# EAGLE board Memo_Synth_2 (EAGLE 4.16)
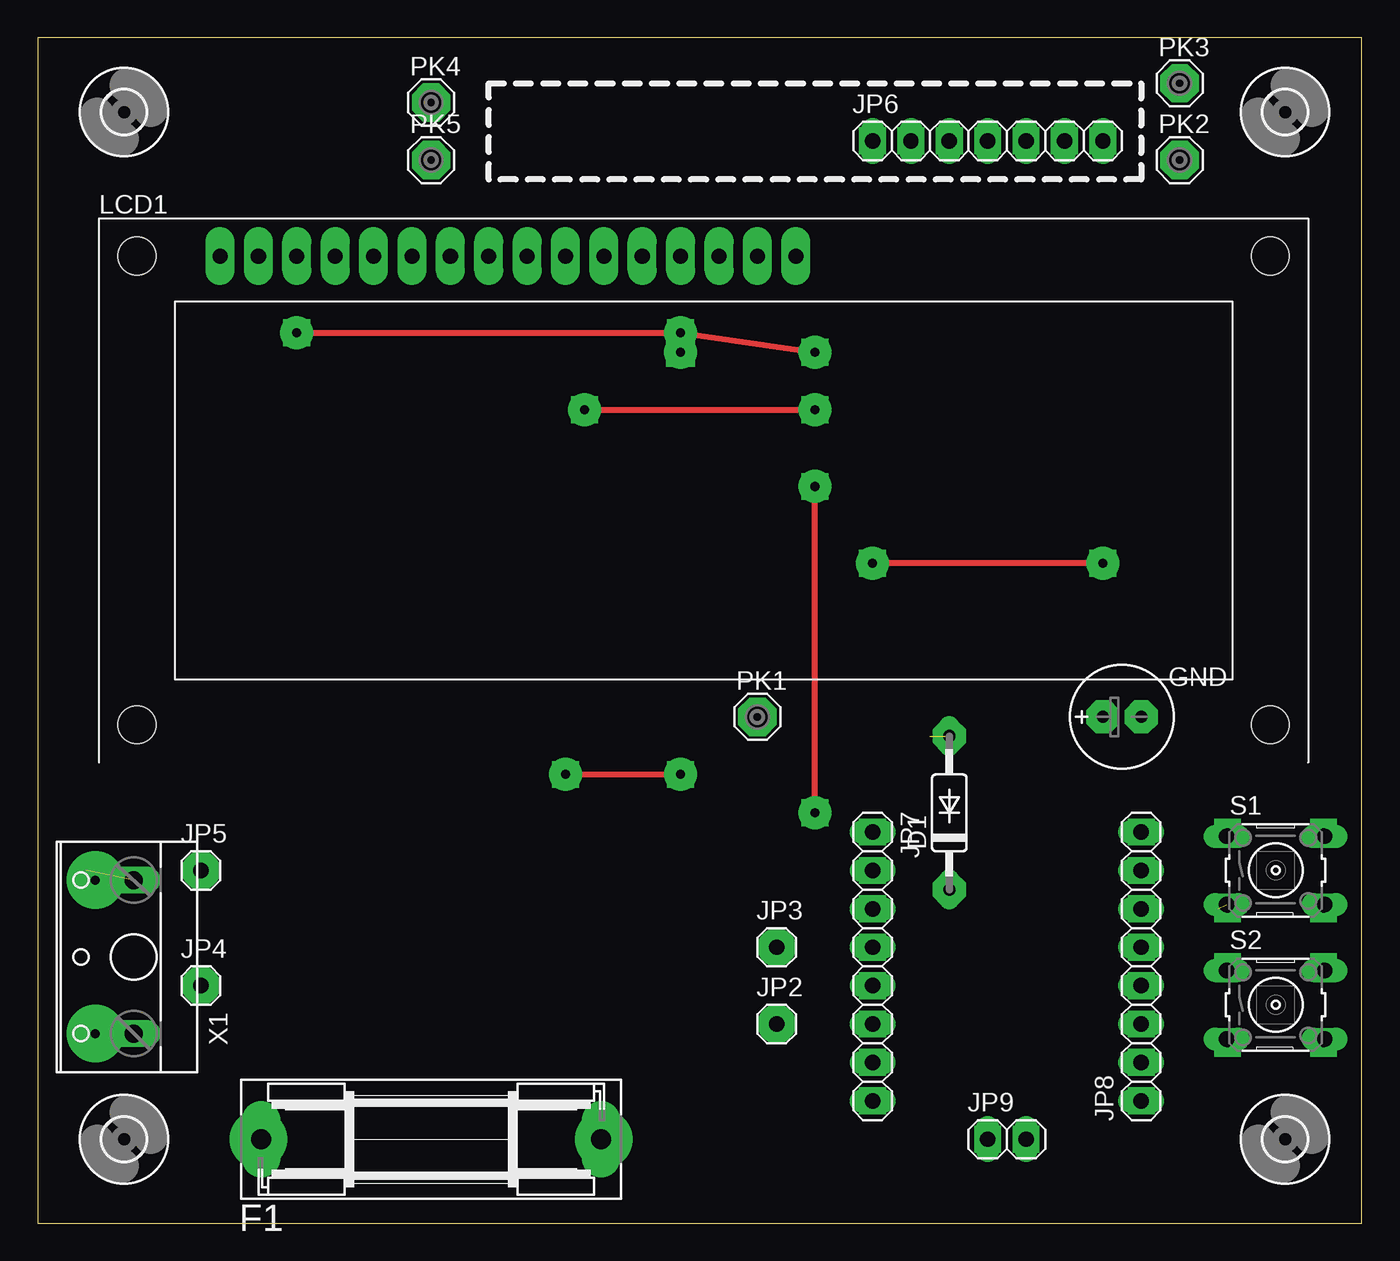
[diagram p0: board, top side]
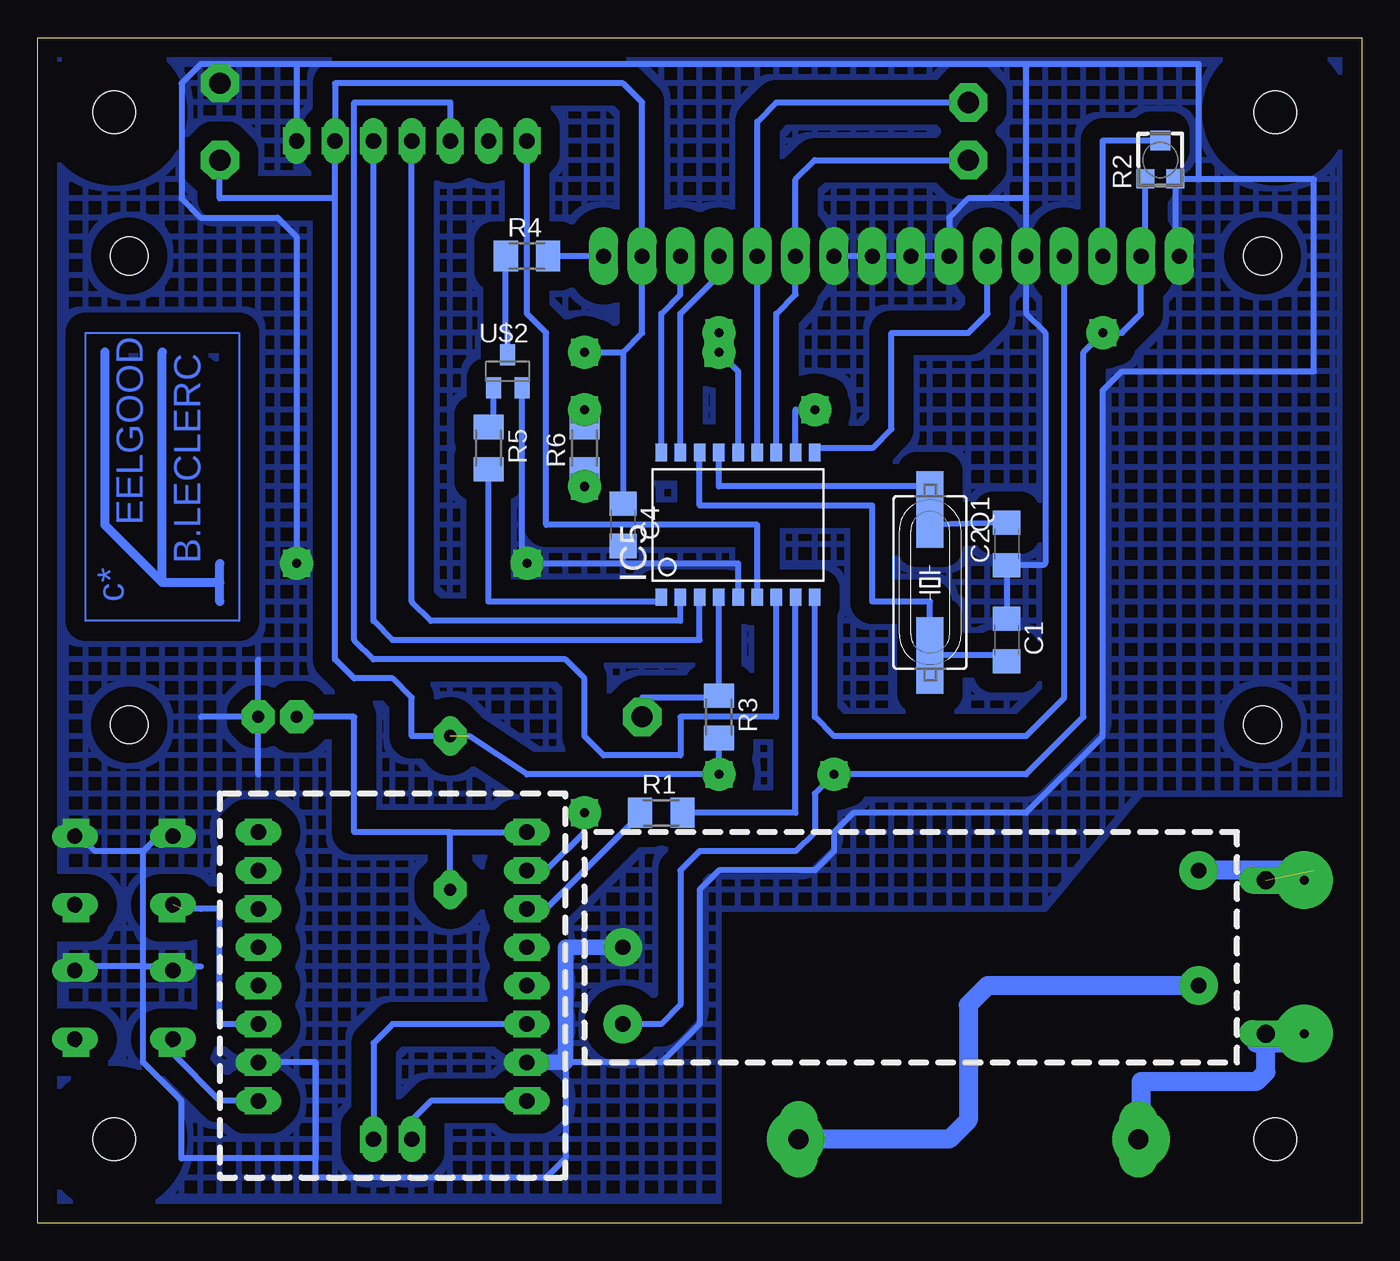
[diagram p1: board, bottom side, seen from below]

Size 87.61 x 78.41 mm. Coordinates in mm from the lower left corner, seen from the top.
Outline: 0,0 87.61,0 87.61,78.41 0,78.41 0,0
Copper layers (1*16): Top 0.035mm / dielectric 1.5mm / Bottom 0.035mm
Design rules "default": minimum track width 10mil, minimum drill 24mil, track to track 8mil, track to pad 8mil, pad to pad 8mil, via to via 8mil, smd to smd 8mil, copper to edge 40mil, drill to drill 8mil, minimum pad ring 10mil, minimum via ring 8mil, stop-mask expansion 4mil, vias tented up to drill 0mil, thermal gap 10mil

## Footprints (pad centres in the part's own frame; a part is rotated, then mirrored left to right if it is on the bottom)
C1206 = smd 1.6 x 1.8: 1 -1.4,0; 2 1.4,0
C2992 = drill 0.813 long: A 5.08,0; C -5.08,0
SH22,5 = drill 1.321 pad 2.54 long: 1 -11.252,0; 2 11.252,0
E2,5-7 = drill 0.813 pad 1.6 round: + -1.27,0 | drill 0.813 pad 1.6 octagon: - 1.27,0
2,8 = hole 2.8: 0,0
SO-18W = smd 0.762 x 1.143: 1 -5.08,-4.788; 2 -3.81,-4.788; 3 -2.54,-4.788; 4 -1.27,-4.788; 5 0,-4.788; 6 1.27,-4.788; 7 2.54,-4.788; 8 3.81,-4.788; 9 5.08,-4.788; 10 5.08,4.788; 11 3.81,4.788; 12 2.54,4.788; 13 1.27,4.788; 14 0,4.788; 15 -1.27,4.788; 16 -2.54,4.788; 17 -3.81,4.788; 18 -5.08,4.788
1X01 = drill 1.016 octagon: 1 0,0
1X07 = drill 1.016 long: 1 -7.62,0; 2 -5.08,0; 3 -2.54,0; 4 0,0; 5 2.54,0; 6 5.08,0; 7 7.62,0
1X08 = drill 1.016 long: 1 -8.89,0; 2 -6.35,0; 3 -3.81,0; 4 -1.27,0; 5 1.27,0; 6 3.81,0; 7 6.35,0; 8 8.89,0
1X02 = drill 1.016 long: 1 -1.27,0; 2 1.27,0
HY-1602F = drill 1 pad 1.93 long: 1 2.54,0; 2 5.08,0; 3 7.62,0; 4 10.16,0; 5 12.7,0; 6 15.24,0; 7 17.78,0; 8 20.32,0; 9 22.86,0; 10 25.4,0; 11 27.94,0; 12 30.48,0; 13 33.02,0; 14 35.56,0; 15 38.1,0; 16 40.64,0 | hole 2.5: -2.96,0; 72.04,0; -2.96,-31; 72.04,-31
SE14 = drill 1.397 pad 2.54 octagon: MP 0,0
SM49 = smd 5.08 x 1.778: 1 -4.826,0; 2 4.826,0
M1206 = smd 1.6 x 2: 1 -1.4,0; 2 1.4,0
RTRIM3103 = smd 1.2 x 1.25: 1 -1,-1.225; 3 1,-1.225 | smd 1.3 x 1.3: 2 0,1.3
B3F-10XX = drill 1.016 long: 1 -3.251,2.261; 2 3.251,2.261; 3 -3.251,-2.261; 4 3.251,-2.261
SOT23-BEC = smd 1 x 1.4: B -0.95,-1.1; C 0,1.1; E 0.95,-1.1
W237-2N = drill 1.194 long: 1 -5.08,-0.635; 2 5.08,-0.635

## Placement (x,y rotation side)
C1  22p  [C1206]  23.49,38.57 270 bottom
C2  22p  [C1206]  23.49,44.92 90 bottom
C4  0.1  [C1206]  48.89,46.19 270 bottom
D1  1N4004  [C2992]  60.32,27.14 90 top
F1  0.5AT  [SH22,5]  26.03,5.55 0 top
GND  [E2,5-7]  71.75,33.49 0 top
H5  MOUNT-HOLE2.8  [2,8]  82.54,5.55 0 top
H6  MOUNT-HOLE2.8  [2,8]  5.71,5.55 0 top
H7  MOUNT-HOLE2.8  [2,8]  5.71,73.49 0 top
H8  MOUNT-HOLE2.8  [2,8]  82.54,73.49 0 top
IC5  PIC16F88ASO  [SO-18W]  41.27,46.19 0 bottom
JP2  [1X01]  48.89,13.17 0 top
JP3  [1X01]  48.89,18.25 0 top
JP4  [1X01]  10.79,15.71 0 top
JP5  [1X01]  10.79,23.33 0 top
JP6  [1X07]  62.86,71.59 0 top
JP7  [1X08]  55.24,16.98 270 top
JP8  [1X08]  73.02,16.98 90 top
JP9  [1X02]  64.13,5.55 0 top
LCD1  LCD_2X16_SIL  [HY-1602F]  9.52,63.97 0 top
PK1  SE14  [SE14]  47.62,33.49 0 top
PK2  SE14  [SE14]  75.56,70.32 0 top
PK3  SE14  [SE14]  75.56,75.4 0 top
PK4  SE14  [SE14]  26.03,74.13 0 top
PK5  SE14  [SE14]  26.03,70.32 0 top
Q1  4Mhz  [SM49]  28.57,42.38 270 bottom
R1  1K  [M1206]  46.35,27.14 0 bottom
R2  10K  [RTRIM3103]  13.33,70.32 0 bottom
R3  100k  [M1206]  42.54,33.49 270 bottom
R4  100  [M1206]  55.24,63.97 0 bottom
R5  22k  [M1206]  57.78,51.27 270 bottom
R6  1K  [M1206]  51.43,51.27 90 bottom
S1  [B3F-10XX]  81.91,23.33 0 top
S2  [B3F-10XX]  81.91,14.44 0 top
U$2  2N2222_SOT23  [SOT23-BEC]  56.51,56.35 0 bottom
U$4  [LITTFEEL]  71.75,42.38 90 bottom
X1  [W237-2N]  5.71,17.61 90 top

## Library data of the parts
C1 C2 C4 GND R1-R6 = rcl
D1 = diode
F1 = fuse
H5-H8 = holes
IC5 = microchip
JP2-JP9 = pinhead
LCD1 = lcd_2x16_led_backlight
PK1-PK5 = solpad
Q1 = crystal
S1 S2 = switch-omron
U$2 = transistor
U$4 = LOGO
X1 = con-wago-508

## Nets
D4: IC5.12 LCD1.11 PK5.MP
D5: IC5.13 LCD1.12 PK4.MP
D6: IC5.17 LCD1.13
D7: IC5.18 LCD1.14
E: IC5.10 LCD1.6
GND: C1.1 C2.1 C4.2 IC5.5 JP3.1 JP6.7 JP7.7 JP8.2 LCD1.1 LCD1.5 LCD1.7 LCD1.8 LCD1.9 LCD1.10 PK3.MP R2.3 S1.1 S1.2 S2.1 S2.2 U$2.E
IN1: IC5.3 JP6.5
IN2: IC5.2 JP6.4
IN3: IC5.7 JP6.3
IO1: JP8.1 S2.3
IO2: JP8.3 S1.3
LED: IC5.1 R5.2
MCLR: IC5.4 PK1.MP R3.1
N$1: C1.2 IC5.16 Q1.2
N$2: C2.2 IC5.15 Q1.1
N$3: R4.1 U$2.C
N$4: JP7.2
N$6: LCD1.16 R4.2
N$7: F1.1 X1.1
N$8: F1.2 JP4.1
N$9: R5.1 U$2.B
N$10: JP5.1 X1.2
N$14: C4.1 IC5.14 JP2.1 JP6.6 LCD1.2 LCD1.15 PK2.MP R2.1 R3.2
N$71: D1.C GND.+
RS: IC5.9 LCD1.4
S$3: IC5.11
S$4: JP7.3
SPK1: JP7.6 JP9.2
SPK2: JP7.8 JP9.1
STB: IC5.6 JP6.1
TX: IC5.8
VO: LCD1.3 R2.2

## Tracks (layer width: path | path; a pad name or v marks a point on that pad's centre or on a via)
D4
  Bottom 0.406: IC5.12 38.73,60.16 37.46,61.43 LCD1.11 37.46,69.05 36.19,70.32 PK5.MP
D5
  Bottom 0.406: IC5.13 LCD1.12 40,72.86 38.73,74.13 PK4.MP
D6
  Bottom 0.406: LCD1.13 42.54,62.7 45.08,60.16 IC5.17
D7
  Bottom 0.406: LCD1.14 45.08,61.43 46.35,60.16 IC5.18
E
  Bottom 0.406: LCD1.6 24.76,60.16 26.03,58.89 31.11,58.89 31.11,52.54 32.38,51.27 36.19,51.27 IC5.10
GND  (via drill 0.5 pad 1.78, 0.5 pad 2.18, 0.5 pad 2.54, 0.6 pad 2.18)
  Top 0.406: v70.48,43.65 v55.24,43.65
  Bottom 0.406: LCD1.1 12.33,64.24 R2.3 12.11,69.09 12.06,69.05 10.79,69.05 | LCD1.10 LCD1.9 LCD1.8 LCD1.7 27.3,66.51 26.03,67.78 22.22,67.78 | 22.22,67.78 LCD1.5 22.22,60.16 20.95,58.89 20.95,43.65 21.08,43.52 C2.1 | 22.22,76.67 22.22,67.78 | 10.79,69.05 10.79,76.67 22.22,76.67 | 70.48,76.67 JP6.7 | U$2.E 55.56,43.97 v55.24,43.65 48.89,43.65 | 48.89,43.65 41.27,43.65 IC5.5 41.27,41.11 | 48.89,43.65 C4.2 | S1.1 79.65,25.59 80.64,24.6 | 80.64,16.98 80.64,24.6 | C2.1 23.49,43.65 | C2.1 C1.1 | 10.79,69.05 3.17,69.05 3.17,56.35 15.87,56.35 17.14,55.08 17.14,32.22 22.22,27.14 33.65,27.14 34.92,25.87 34.92,24.6 36.19,23.33 42.54,23.33 43.81,22.06 43.81,13.17 46.35,10.63 52.7,10.63 52.7,4.28 53.97,3.01 69.21,3.01 69.21,10.63 | 80.64,16.98 76.83,16.98 | 69.21,10.63 69.21,4.28 78.1,4.28 78.1,8.09 80.64,10.63 80.64,16.98 | 22.22,76.67 70.48,76.67 | 70.48,76.67 74.29,76.67 | 74.29,76.67 75.56,76.67 PK3.MP | 74.29,76.67 76.83,76.67 78.1,75.4 78.1,67.78 76.83,66.51 71.75,66.51 70.48,65.24 v70.48,43.65 | 69.21,10.63 JP8.2 | 80.64,16.98 v85.08,16.98 | 80.64,24.6 83.81,24.6 v85.08,25.87 | v73.02,33.49 76.83,33.49 | v73.02,33.49 73.02,37.3 | 73.02,29.68 v73.02,33.49
  Bottom 1.016: JP3.1 52.7,18.25 52.7,10.63 JP7.7
  other vias: 75.56,75.4 70.48,71.59 34.92,63.97 32.38,63.97 29.84,63.97 27.3,63.97 22.22,63.97 12.06,63.97 73.02,10.63 55.24,10.63 48.89,18.25 78.73,25.87 78.73,16.98
  pour Bottom (isolate 1.27, no thermals, hatched): 0.63,28.41 0.63,77.94 86.99,77.94 86.99,0.47 42.54,0.47 42.54,20.79 20.95,20.79 14.6,28.41
IN1
  Bottom 0.406: JP6.5 65.4,39.84 64.13,38.57 43.81,38.57 IC5.3
IN2
  Bottom 0.406: JP6.4 62.86,41.11 61.59,39.84 45.08,39.84 45.08,41.11 IC5.2
IN3
  Bottom 0.406: JP6.3 60.32,74.13 66.67,74.13 66.67,38.57 65.4,37.3 52.7,37.3 51.43,36.03 51.43,32.22 50.16,30.95 45.08,30.95 45.08,33.49 38.73,33.49 IC5.7
IO1
  Bottom 0.406: S2.3 78.66,11.19 75.56,8.09 JP8.1
IO2  (1 unrouted)
  Bottom 0.406: JP8.3 75.56,13.17 75.56,20.79 76.83,20.79 78.1,20.79
LED
  Bottom 0.406: R5.2 57.78,41.11 46.35,41.11 IC5.1
MCLR
  Bottom 0.406: IC5.4 R3.1 42.54,34.76 47.62,34.76 PK1.MP
N$1
  Bottom 0.406: IC5.16 43.81,47.46 32.38,47.46 32.38,41.11 28.57,41.11 Q1.2 23.74,37.55 23.49,37.3 C1.2
N$2
  Bottom 0.406: IC5.15 42.54,48.73 28.57,48.73 | 28.57,47.46 Q1.1 28.57,48.73 | C2.2 28.57,46.19 28.57,48.73
N$3
  Bottom 0.406: U$2.C 56.51,58.89 56.64,59.02 R4.1
N$4  (via drill 0.6 pad 2.18)
  Top 0.406: v51.43,27.14 v51.43,48.73
  Bottom 0.406: v51.43,27.14 51.43,25.87 53.97,23.33 JP7.2
N$5  (via drill 0.5 pad 2.54)
  other vias: 48.89,13.17
N$6
  Bottom 0.406: 53.97,63.97 R4.2 LCD1.16
N$7
  Bottom 1.27: X1.1 6.34,10 6.98,9.36 14.6,9.36 14.6,5.55 F1.1
N$8
  Bottom 1.27: JP4.1 24.76,15.71 26.03,14.44 26.03,6.82 27.3,5.55 F1.2 37.46,5.55
N$9
  Bottom 0.406: R5.1 57.78,52.54 57.46,52.86 U$2.B
N$10  (1 unrouted)
  Bottom 1.27: 3.17,23.33 JP5.1
N$11
  Bottom 1.27: 6.98,11.9 4.44,11.9 3.17,11.9
N$13  (via drill 0.5 pad 2.54)
  Bottom 1.27: v10.79,15.71 24.76,15.71 26.03,14.44 26.03,6.82 27.3,5.55 37.46,5.55
N$14  (via drill 0.5 pad 2.18, 0.6 pad 1.93, 0.6 pad 2.18)  (1 unrouted)
  Top 0.406: v51.43,57.62 v42.54,58.89 v17.14,58.89 | v34.92,29.68 v42.54,29.68
  Bottom 0.406: PK2.MP 75.56,67.78 67.94,67.78 | 67.94,67.78 JP6.6 67.94,75.4 48.89,75.4 47.62,74.13 LCD1.15 47.62,58.89 48.89,57.62 | 67.94,67.78 67.94,37.3 66.67,36.03 64.13,36.03 62.86,34.76 62.86,32.22 59.05,32.22 55.24,29.68 v42.54,29.68 R3.2 | JP2.1 46.35,13.17 45.08,14.44 45.08,23.33 43.81,24.6 37.46,24.6 36.19,25.87 36.19,28.41 v34.92,29.68 22.22,29.68 18.41,33.49 18.41,57.62 v17.14,58.89 15.87,58.89 14.6,60.16 LCD1.2 14.33,64.24 R2.1 | 48.89,57.62 C4.1 | IC5.14 41.27,56.35 v42.54,57.62 v42.54,58.89 | v51.43,57.62 48.89,57.62
  other vias: 60.32,32.22
N$15  (via drill 0.5 pad 2.54)
  other vias: 10.79,23.33
N$16  (via drill 0.6 pad 3.81)
  other vias: 3.8,22.7
N$18  (via drill 0.6 pad 3.81)
  other vias: 3.8,12.54
N$19  (via drill 0.6 pad 3.81)
  other vias: 37.46,5.55
N$20  (via drill 0.6 pad 3.81)
  other vias: 14.6,5.55
N$23  (via drill 0.5 pad 1.78)
  other vias: 45.08,63.97
N$24  (via drill 0.5 pad 1.78)
  other vias: 40,63.97
N$25  (via drill 0.5 pad 1.78)
  other vias: 42.54,63.97
N$26  (via drill 0.5 pad 1.78)
  other vias: 50.16,63.97
N$27  (via drill 0.5 pad 1.78)
  other vias: 47.62,63.97
N$29  (via drill 0.5 pad 1.78)
  other vias: 19.68,63.97
N$33  (via drill 0.5 pad 1.78)
  other vias: 37.46,63.97
N$34  (via drill 0.5 pad 1.78)
  other vias: 24.76,63.97
N$36  (via drill 0.5 pad 1.78)
  other vias: 17.14,63.97
N$37  (via drill 0.5 pad 1.78)
  other vias: 14.6,63.97
N$39  (via drill 0.5 pad 1.78)
  other vias: 75.56,70.32
N$40  (via drill 0.5 pad 1.78)
  other vias: 85.08,11.9
N$41  (via drill 0.5 pad 1.78)
  other vias: 26.03,70.32
N$42  (via drill 0.5 pad 1.78)
  other vias: 26.03,74.13
N$43  (via drill 0.5 pad 1.78)
  other vias: 47.62,33.49
N$44  (via drill 0.5 pad 1.78)
  other vias: 55.24,71.59
N$45  (via drill 0.5 pad 1.78)
  other vias: 57.78,71.59
N$46  (via drill 0.5 pad 1.78)
  other vias: 60.32,71.59
N$47  (via drill 0.5 pad 1.78)
  other vias: 62.86,71.59
N$48  (via drill 0.5 pad 1.78)
  other vias: 65.4,71.59
N$49  (via drill 0.5 pad 1.78)
  other vias: 67.94,71.59
N$51  (via drill 0.5 pad 1.78)
  other vias: 51.43,57.62
N$52  (via drill 0.5 pad 1.78)
  other vias: 42.54,58.89
N$53  (via drill 0.5 pad 1.78)
  other vias: 17.14,58.89
N$54  (via drill 0.5 pad 1.78)
  other vias: 36.19,53.81
N$55  (via drill 0.5 pad 1.78)
  other vias: 51.43,53.81
N$56  (via drill 0.5 pad 1.78)
  other vias: 51.43,48.73
N$57  (via drill 0.5 pad 1.78)
  other vias: 51.43,27.14
N$58  (via drill 0.5 pad 1.78)
  other vias: 85.08,20.79
N$60  (via drill 0.5 pad 1.78)
  other vias: 62.86,5.55
N$61  (via drill 0.5 pad 1.78)
  other vias: 65.4,5.55
N$62  (via drill 0.5 pad 1.78)
  other vias: 34.92,29.68
N$63  (via drill 0.5 pad 1.78)
  other vias: 42.54,29.68
N$64  (via drill 0.5 pad 1.78)
  other vias: 73.02,25.87
N$65  (via drill 0.5 pad 1.78)
  other vias: 73.02,23.33
N$66  (via drill 0.5 pad 1.78)
  other vias: 73.02,15.71
N$67  (via drill 0.5 pad 1.78)
  other vias: 73.02,8.09
N$68  (via drill 0.5 pad 1.78)
  other vias: 55.24,8.09
N$69  (via drill 0.5 pad 1.78)
  other vias: 55.24,15.71
N$70  (via drill 0.5 pad 1.78)
  other vias: 55.24,20.79
N$71  (via drill 0.5 pad 1.78, 0.5 pad 2.18)
  Bottom 0.406: 60.32,25.87 v55.24,25.87 | 60.32,25.87 66.67,25.87 66.67,33.49 GND.+ | D1.C 60.32,25.87
  other vias: 60.32,22.06
N$72  (via drill 0.5 pad 1.78)
  other vias: 55.24,23.33
N$73  (via drill 0.5 pad 1.78)
  other vias: 55.24,18.25
N$74  (via drill 0.5 pad 1.78)
  other vias: 55.24,13.17
N$76  (via drill 0.5 pad 1.78)
  other vias: 78.73,11.9
N$77  (via drill 0.5 pad 1.78)
  other vias: 73.02,13.17
N$78  (via drill 0.5 pad 1.78)
  other vias: 73.02,18.25
N$79  (via drill 0.5 pad 1.78)
  other vias: 73.02,20.79
N$80  (via drill 0.5 pad 1.78)
  other vias: 78.73,20.79
RS
  Bottom 0.406: LCD1.4 19.68,34.76 22.22,32.22 34.92,32.22 36.19,33.49 36.19,41.11 IC5.9
S$1  (via drill 0.5 pad 1.93)
  other vias: 42.54,57.62
S$2  (via drill 0.5 pad 2.18)
  other vias: 42.54,57.62
S$3  (via drill 0.6 pad 2.18)
  Top 0.406: v36.19,53.81 v51.43,53.81
  Bottom 0.406: v36.19,53.81 37.46,53.81 IC5.11 37.46,51.27
S$4
  Bottom 0.406: JP7.3 53.97,20.79 47.62,27.14
S$5  (via drill 0.5 pad 2.18)
  other vias: 70.48,33.49
SPK1
  Bottom 0.406: JP7.6 64.13,13.17 65.4,11.9 JP9.2
SPK2
  Bottom 0.406: JP7.8 61.59,8.09 62.86,6.82 JP9.1
STB
  Bottom 0.406: JP6.1 55.24,60.16 53.97,58.89 53.97,46.19 40,46.19 IC5.6 40,41.11
TX
  Bottom 0.406: IC5.8 37.46,27.14 45.08,27.14
VO
  Bottom 0.406: R2.2 17.11,71.62 17.14,71.59 LCD1.3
